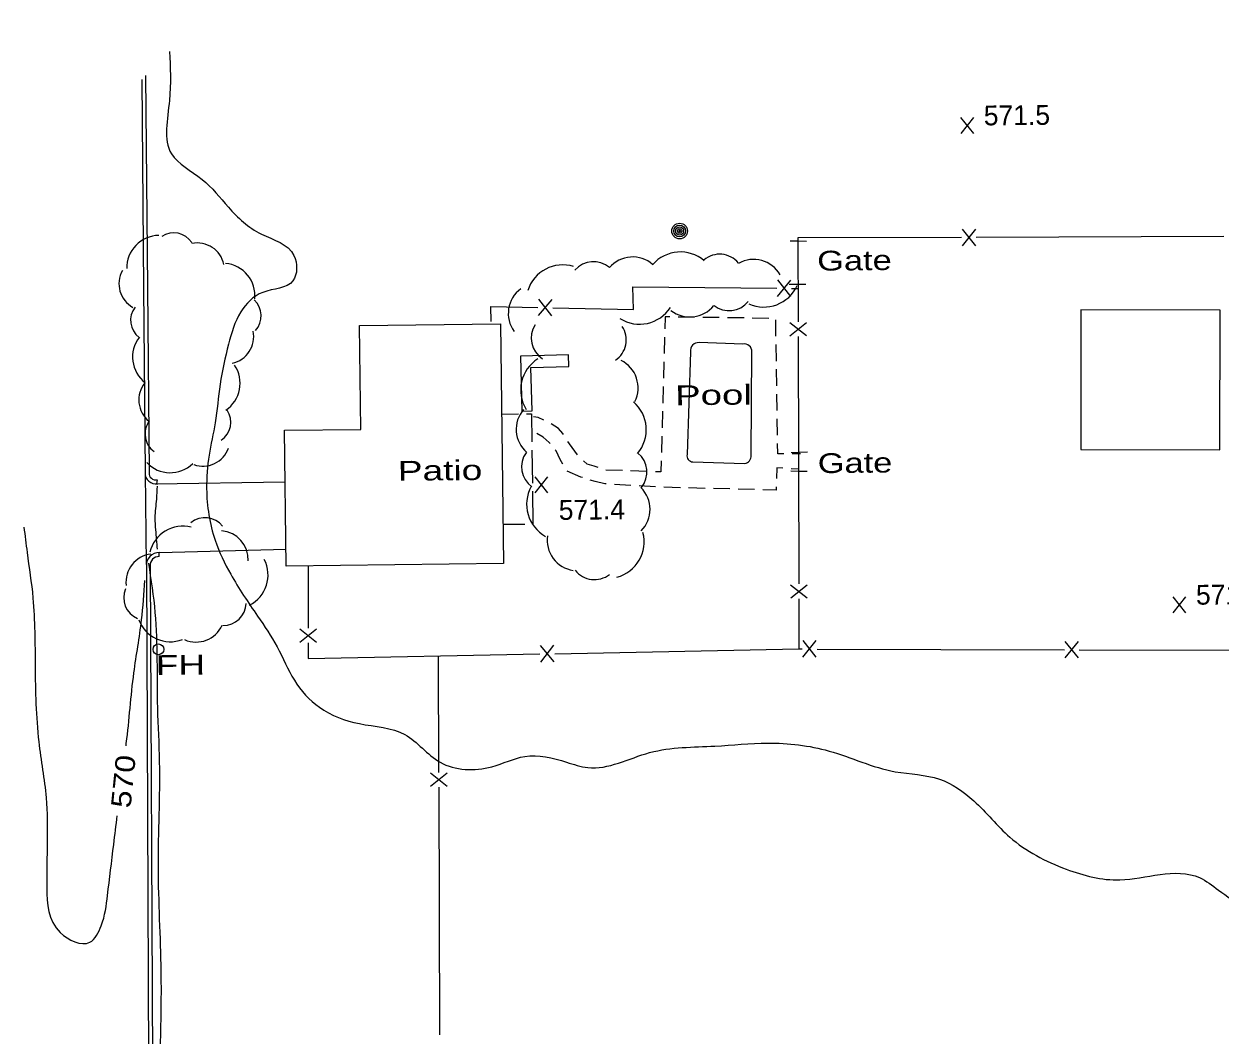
# Model space of a CAD drawing. Extents: x 2361708 to 2370558, y 6977955 to 6991887.
# Drawn here: x 2368271.1 to 2368561.2, y 6990259.1 to 6990504.4 of the extents above; entities that cross this region are included whole.
import ezdxf
from ezdxf.enums import TextEntityAlignment as Align

# ---------------------------------------------------------------- set-up
doc = ezdxf.new("R2010")
doc.units = 0
doc.header["$LTSCALE"] = 1.9
for name, color, linetype, lineweight in [('11', 7, 'Continuous', 25), ('13', 7, 'Continuous', 13), ('14', 7, 'Continuous', 13), ('17', 7, 'Continuous', 25), ('2', 7, 'Continuous', 25), ('20', 7, 'Continuous', 25), ('23', 7, 'Continuous', 25), ('29', 7, 'Continuous', 13), ('31', 7, 'Continuous', 13), ('35', 7, 'Continuous', 13)]:
    doc.layers.add(name, color=color, linetype=linetype, lineweight=lineweight)

msp = doc.modelspace()

# ---------------------------------------------------------------- linework, layer by layer
at = {"layer": '11'}
for points in [[(2368561.178, 6990434.941), (2368527.455, 6990434.98), (2368527.418, 6990401.138), (2368561.14, 6990401.099)], [(2368386.711, 6990431.64), (2368387.434, 6990373.474), (2368334.738, 6990372.822), (2368334.334, 6990405.8), (2368352.773, 6990406.026), (2368352.463, 6990431.224)]]:
    msp.add_lwpolyline(points, close=True, dxfattribs=at)
at = {"layer": '13'}
for p, q in [((2368433.738, 6990433.208), (2368429.737, 6990433.27)), ((2368439.739, 6990433.125), (2368435.738, 6990433.177)), ((2368445.74, 6990433.042), (2368441.739, 6990433.094)), ((2368451.741, 6990432.949), (2368447.74, 6990433.011)), ((2368453.493, 6990428.606), (2368453.425, 6990432.605)), ((2368426.483, 6990428.419), (2368426.371, 6990424.417)), ((2368453.59, 6990422.606), (2368453.522, 6990426.606)), ((2368426.31, 6990422.417), (2368426.198, 6990418.415)), ((2368453.677, 6990416.607), (2368453.619, 6990420.607)), ((2368426.137, 6990416.415), (2368426.026, 6990412.413)), ((2368453.774, 6990410.607), (2368453.706, 6990414.607)), ((2368425.965, 6990410.412), (2368425.853, 6990406.411)), ((2368453.861, 6990404.608), (2368453.803, 6990408.607)), ((2368425.801, 6990404.41), (2368425.69, 6990400.41)), ((2368459.425, 6990400.071), (2368457.424, 6990400.081)), ((2368459.149, 6990396.398), (2368457.149, 6990396.499)), ((2368416.241, 6990396.029), (2368412.239, 6990396.161)), ((2368422.243, 6990395.827), (2368418.242, 6990395.958)), ((2368418.315, 6990392.459), (2368414.323, 6990392.701)), ((2368424.309, 6990392.096), (2368420.316, 6990392.338)), ((2368430.311, 6990391.883), (2368426.31, 6990391.995)), ((2368436.313, 6990391.73), (2368432.312, 6990391.832)), ((2368442.315, 6990391.577), (2368438.314, 6990391.68)), ((2368448.316, 6990391.424), (2368444.315, 6990391.527))]:
    msp.add_line(p, q, dxfattribs=at)
for points in [[(2368427.736, 6990433.301), (2368426.627, 6990433.31), (2368426.544, 6990430.419)], [(2368397.203, 6990408.279), (2368395.838, 6990408.886), (2368394.656, 6990409.045)], [(2368398.697, 6990402.643), (2368398.505, 6990402.881), (2368397.053, 6990404.127), (2368395.534, 6990405.062)], [(2368401.937, 6990404.753), (2368401.765, 6990405.022), (2368400.733, 6990406.232), (2368398.992, 6990407.396)], [(2368405.354, 6990399.826), (2368403.399, 6990402.487), (2368403.023, 6990403.074)], [(2368455.424, 6990400.093), (2368453.934, 6990400.098), (2368453.89, 6990402.608)], [(2368401.796, 6990397.562), (2368401.135, 6990398.706), (2368400.205, 6990400.797), (2368399.962, 6990401.095)], [(2368410.334, 6990396.773), (2368409.39, 6990397.084), (2368407.726, 6990397.558), (2368406.788, 6990398.429)], [(2368425.629, 6990398.409), (2368425.554, 6990395.718), (2368424.244, 6990395.765)], [(2368455.148, 6990396.6), (2368453.717, 6990396.666), (2368453.621, 6990394.105)], [(2368406.537, 6990394.347), (2368406.155, 6990394.473), (2368402.852, 6990395.892)], [(2368412.321, 6990392.822), (2368412.001, 6990392.839), (2368409.666, 6990393.357), (2368408.443, 6990393.745)], [(2368453.54, 6990392.104), (2368453.508, 6990391.293), (2368450.317, 6990391.373)]]:
    msp.add_lwpolyline(points, dxfattribs=at)
at = {"layer": '14'}
for p, q in [((2368387.01, 6990409.722), (2368391.009, 6990409.78)), ((2368394.323, 6990401.011), (2368394.428, 6990393.012)), ((2368394.458, 6990391.012), (2368394.564, 6990383.012)), ((2368392.564, 6990382.983), (2368387.474, 6990382.925))]:
    msp.add_line(p, q, dxfattribs=at)
msp.add_lwpolyline([(2368393.009, 6990409.809), (2368394.199, 6990409.82), (2368394.293, 6990403.011)], dxfattribs=at)
at = {"layer": '17'}
for p, q in [((2368498.668, 6990454.547), (2368501.886, 6990450.557)), ((2368501.868, 6990454.557), (2368498.686, 6990450.547)), ((2368562.078, 6990452.78), (2368502.077, 6990452.589)), ((2368453.871, 6990438.28), (2368457.113, 6990442.251)), ((2368457.071, 6990438.25), (2368453.913, 6990442.28)), ((2368457.293, 6990440.212), (2368458.922, 6990440.197)), ((2368395.922, 6990433.608), (2368399.195, 6990437.549)), ((2368399.123, 6990433.548), (2368395.994, 6990437.609)), ((2368456.861, 6990431.947), (2368460.872, 6990428.756)), ((2368456.871, 6990428.748), (2368460.861, 6990431.956)), ((2368458.854, 6990428.547), (2368459.025, 6990368.545)), ((2368340.008, 6990372.832), (2368340.011, 6990357.832)), ((2368457.046, 6990368.346), (2368461.057, 6990365.155)), ((2368457.057, 6990365.146), (2368461.046, 6990368.354)), ((2368459.029, 6990364.945), (2368459.065, 6990352.775)), ((2368338.043, 6990357.633), (2368342.044, 6990354.431)), ((2368338.043, 6990354.433), (2368342.043, 6990357.631)), ((2368399.702, 6990349.67), (2368396.424, 6990353.608)), ((2368396.502, 6990349.609), (2368399.624, 6990353.669)), ((2368460.044, 6990350.804), (2368463.256, 6990354.795)), ((2368463.244, 6990350.794), (2368460.056, 6990354.804)), ((2368463.455, 6990352.767), (2368523.46, 6990352.598)), ((2368523.639, 6990350.629), (2368526.851, 6990354.62)), ((2368526.839, 6990350.62), (2368523.65, 6990354.629)), ((2368371.756, 6990322.842), (2368371.679, 6990350.853)), ((2368527.06, 6990352.592), (2368582.594, 6990352.44)), ((2368373.738, 6990319.441), (2368369.727, 6990322.633)), ((2368373.727, 6990322.641), (2368369.738, 6990319.433)), ((2368371.931, 6990259.241), (2368371.77, 6990319.242))]:
    msp.add_line(p, q, dxfattribs=at)
for points in [[(2368456.932, 6990451.789), (2368458.933, 6990451.748), (2368460.933, 6990451.707)], [(2368498.477, 6990452.575), (2368458.776, 6990452.447), (2368458.839, 6990432.147)], [(2368399.365, 6990435.511), (2368418.969, 6990435.137), (2368418.767, 6990440.595), (2368453.692, 6990440.248)], [(2368460.714, 6990441.155), (2368458.714, 6990441.155), (2368456.713, 6990441.156)], [(2368384.405, 6990432.188), (2368384.371, 6990435.798), (2368395.764, 6990435.576)], [(2368457.171, 6990400.419), (2368459.17, 6990400.508), (2368461.17, 6990400.597)], [(2368461.085, 6990395.816), (2368459.085, 6990395.837), (2368457.085, 6990395.858)], [(2368340.015, 6990354.232), (2368340.011, 6990350.492), (2368396.263, 6990351.567)], [(2368399.863, 6990351.631), (2368459.065, 6990352.775), (2368459.855, 6990352.772)]]:
    msp.add_lwpolyline(points, dxfattribs=at)
at = {"layer": '2'}
for p, q in [((2368300.48, 6990395.537), (2368300.782, 6990373.299)), ((2368303.387, 6990393.795), (2368303.226, 6990392.844)), ((2368302.976, 6990392.811), (2368334.423, 6990393.31)), ((2368303.924, 6990375.179), (2368303.915, 6990376.139)), ((2368303.985, 6990376.14), (2368334.679, 6990376.972)), ((2368300.797, 6990372.76), (2368301.377, 6990243.559)), ((2368301.757, 6990372.768), (2368302.336, 6990243.568))]:
    msp.add_line(p, q, dxfattribs=at)
for points in [[(2368299.672, 6990490.884), (2368300.144, 6990440.316), (2368300.48, 6990395.537)], [(2368300.623, 6990491.863), (2368301.104, 6990440.325), (2368301.44, 6990395.546)]]:
    msp.add_lwpolyline(points, dxfattribs=at)
msp.add_lwpolyline([(2368394.342, 6990410.522), (2368394.062, 6990421), (2368403.29, 6990421.238), (2368403.213, 6990424.127), (2368391.505, 6990423.805), (2368391.872, 6990410.458)], close=True, dxfattribs=at)
for centre, radius, start, end in [((2368303.094, 6990395.422), 2.616, 177.47443, 280.17534), ((2368303.094, 6990395.422), 1.656, 177.47443, 280.17534), ((2368303.802, 6990373.12), 3.025, 86.54286, 186.84661), ((2368303.802, 6990373.12), 2.065, 86.54286, 186.84661)]:
    msp.add_arc(centre, radius, start, end, dxfattribs=at)
at = {"layer": '20'}
for centre, radius in [((2368430.129, 6990454.134), 1.9), ((2368430.129, 6990454.134), 1.442), ((2368430.129, 6990454.134), 0.973), ((2368430.129, 6990454.134), 0.539), ((2368430.129, 6990454.134), 0.192), ((2368303.718, 6990352.686), 1.3)]:
    msp.add_circle(centre, radius, dxfattribs=at)
at = {"layer": '23'}
for p, q in [((2368445.43, 6990426.729), (2368434.856, 6990427.068)), ((2368432.798, 6990424.838), (2368431.915, 6990399.939)), ((2368447.477, 6990399.747), (2368447.649, 6990424.83)), ((2368433.362, 6990398.142), (2368445.876, 6990397.742))]:
    msp.add_line(p, q, dxfattribs=at)
for centre, radius, start, end in [((2368434.691, 6990425.157), 1.919, 85.05823, 189.54067), ((2368445.789, 6990424.902), 1.861, 357.78805, 101.09945), ((2368433.414, 6990399.669), 1.524, 169.81041, 268.02108), ((2368445.587, 6990399.612), 1.893, 278.78143, 4.0714)]:
    msp.add_arc(centre, radius, start, end, dxfattribs=at)
at = {"layer": '29'}
for centre, radius, start, end in [((2368303.942, 6990445.159), 7.903, 91.06933, 181.06933), ((2368307.392, 6990448.428), 5.265, 33.15376, 123.15376), ((2368313.173, 6990444.638), 6.589, 11.79409, 101.79409), ((2368430.323, 6990440.162), 8.889, 49.37239, 139.37239), ((2368439.821, 6990442.594), 5.922, 39.61492, 129.61492), ((2368319.233, 6990438.419), 7.903, 354.50006, 84.50006), ((2368401.773, 6990437.033), 8.889, 72.64004, 162.64004), ((2368409.225, 6990440.768), 5.922, 49.24255, 139.24255), ((2368418.731, 6990440.423), 7.411, 49.24421, 139.24421), ((2368448.063, 6990439.836), 7.411, 29.65659, 119.65659), ((2368300.731, 6990441.361), 6.589, 150.90885, 240.90885), ((2368395.982, 6990434.109), 7.411, 126.01755, 216.01755), ((2368450.553, 6990444.58), 8.889, 245.62156, 335.62156), ((2368323.389, 6990433.537), 5.265, 317.60113, 47.60113), ((2368442.14, 6990440.738), 5.922, 231.62598, 321.62598), ((2368302.24, 6990432.489), 5.265, 142.33763, 232.33763), ((2368420.429, 6990440.426), 8.889, 237.30302, 327.30302), ((2368432.638, 6990440.694), 7.411, 231.50118, 321.50118), ((2368400.066, 6990428.123), 5.922, 146.89056, 236.89056), ((2368305.352, 6990423.568), 7.903, 142.333, 232.333), ((2368320.236, 6990428.504), 6.589, 282.09717, 12.09717), ((2368411.25, 6990427.71), 5.922, 303.74033, 33.74033), ((2368400.469, 6990415.608), 8.889, 122.07052, 212.07052), ((2368412.643, 6990416.083), 7.411, 333.68994, 63.68994), ((2368315.637, 6990417.223), 7.903, 303.95871, 33.95871), ((2368305.554, 6990413.16), 6.589, 141.21701, 231.21701), ((2368397.904, 6990406.056), 7.411, 139.32923, 229.32923), ((2368413.143, 6990405.963), 8.889, 319.43859, 49.43859), ((2368305.747, 6990404.923), 5.265, 144.16055, 234.16055), ((2368316.015, 6990407.773), 5.265, 303.37291, 33.37291), ((2368314.531, 6990403.702), 6.589, 250.32566, 340.32566), ((2368397.712, 6990396.964), 5.922, 144.75484, 234.75484), ((2368416.263, 6990395.669), 5.922, 320.90958, 50.90958), ((2368306.591, 6990403.43), 7.903, 223.68311, 313.68311), ((2368401.916, 6990387.869), 8.889, 151.05697, 241.05697), ((2368415.537, 6990386.62), 7.411, 315.4291, 45.4291), ((2368309.65, 6990374.298), 8.251, 76.07497, 166.07497), ((2368315.011, 6990379.098), 5.497, 38.74011, 128.74011), ((2368318.599, 6990374.555), 6.879, 356.59397, 86.59397), ((2368405.428, 6990379.147), 7.411, 171.41552, 261.41552), ((2368412.633, 6990378.792), 8.889, 284.72387, 14.72387), ((2368302.718, 6990368.963), 6.879, 96.63949, 186.63949), ((2368322.049, 6990370.765), 8.251, 296.98324, 26.98324), ((2368409.473, 6990375.515), 5.922, 217.98232, 307.98232), ((2368300.801, 6990365.216), 5.497, 156.68792, 246.68792), ((2368319.506, 6990363.994), 5.497, 268.21911, 358.21911), ((2368306.652, 6990362.783), 8.251, 200.75299, 290.75299), ((2368312.859, 6990361.334), 6.879, 246.14099, 336.14099)]:
    msp.add_arc(centre, radius, start, end, dxfattribs=at)
at = {"layer": '31'}
for p, q in [((2368501.477, 6990477.784), (2368498.36, 6990481.635)), ((2368498.397, 6990477.755), (2368501.44, 6990481.665)), ((2368398.201, 6990390.667), (2368395.084, 6990394.518)), ((2368395.121, 6990390.638), (2368398.164, 6990394.547)), ((2368552.926, 6990361.549), (2368549.809, 6990365.399)), ((2368549.846, 6990361.519), (2368552.889, 6990365.429))]:
    msp.add_line(p, q, dxfattribs=at)
at = {"layer": '31', "lineweight": 25}
for points in [[(2368303.467, 6990376.975), (2368303.102, 6990381.652), (2368302.934, 6990384.62), (2368303.321, 6990389.124), (2368303.471, 6990392.256)], [(2368271.104, 6990382.327), (2368271.873, 6990376.194), (2368273.288, 6990365.137), (2368273.825, 6990348.652), (2368274.71, 6990330.269), (2368276.48, 6990316.705), (2368276.647, 6990294.905), (2368279.89, 6990284.026), (2368287.073, 6990281.664), (2368289.856, 6990285.651), (2368291.386, 6990293.006), (2368292.878, 6990305.371), (2368293.752, 6990312.339)], [(2368303.819, 6990241.232), (2368304.159, 6990253.776), (2368304.401, 6990274.559), (2368303.721, 6990299.874), (2368304.018, 6990325.408), (2368303.563, 6990338.504), (2368302.973, 6990361.589), (2368301.369, 6990373.555)], [(2368295.86, 6990329.32), (2368295.935, 6990329.891), (2368297.781, 6990347.02), (2368299.64, 6990359.818), (2368300.409, 6990369.405)]]:
    msp.add_spline(points, degree=3, dxfattribs=at)
at = {"layer": '35'}
for points in [[(2368544.877, 6990563.132), (2368536.747, 6990557.784), (2368526.442, 6990554.096), (2368517.961, 6990553.105), (2368508.153, 6990552.892), (2368494.789, 6990553.254), (2368479.151, 6990554.966), (2368465.744, 6990555.668), (2368454.555, 6990553.351), (2368443.478, 6990546.746), (2368435.844, 6990539.773), (2368438.47, 6990536.978), (2368448.583, 6990534.714), (2368464.262, 6990534.863), (2368481.698, 6990535.369), (2368505.619, 6990536.417), (2368521.205, 6990534.815), (2368537.105, 6990535.986), (2368549.594, 6990538.266), (2368558.375, 6990539.189), (2368564.618, 6990534.678), (2368567.629, 6990524.177), (2368568.907, 6990512.768), (2368571.719, 6990493.614), (2368573.061, 6990472.486), (2368573.839, 6990459.092), (2368574.341, 6990445.127), (2368576.998, 6990431.881), (2368576.21, 6990420.043), (2368576.637, 6990402.516), (2368578.913, 6990390.297), (2368580.542, 6990378.922), (2368580.936, 6990372.226), (2368582.356, 6990369.019), (2368584.836, 6990370.143), (2368584.866, 6990370.123)], [(2368983.929, 6990531.529), (2368979.435, 6990519.356), (2368975.701, 6990506), (2368972.153, 6990495.326), (2368965.023, 6990482.667), (2368952.28, 6990464.985), (2368944.692, 6990449.112), (2368936.279, 6990436.661), (2368930.708, 6990428.388), (2368926.974, 6990420.332), (2368923.178, 6990407.345), (2368925.818, 6990397.9), (2368929.492, 6990388.004), (2368932.253, 6990381.66), (2368935.154, 6990377.288), (2368935.872, 6990367.074), (2368936.658, 6990350.711), (2368934.899, 6990336.894), (2368925.545, 6990315.203), (2368919.061, 6990298.721), (2368917.665, 6990291.017), (2368922.007, 6990291.848), (2368928.932, 6990298.725), (2368940.303, 6990308.073), (2368954.807, 6990321.422), (2368956.934, 6990318.642), (2368952.658, 6990309.771), (2368947.879, 6990300.145), (2368939.818, 6990283.488), (2368927.075, 6990259.465), (2368910.767, 6990240.319), (2368886.835, 6990212.09), (2368866.726, 6990187.627), (2368845.138, 6990163.161), (2368822.496, 6990139.104), (2368799.648, 6990117.845), (2368778.178, 6990104.05), (2368756.592, 6990085.654), (2368734.588, 6990065.974), (2368713.09, 6990048.828), (2368704.692, 6990045.508), (2368705.15, 6990046.662), (2368709.481, 6990052.884), (2368718.059, 6990061.596), (2368727.733, 6990071.708), (2368736.854, 6990082.166), (2368748.659, 6990097.399), (2368759.795, 6990109.476), (2368764.382, 6990117.239), (2368763.943, 6990120.186), (2368757.319, 6990118.552), (2368746.862, 6990109.793), (2368726.432, 6990091.817), (2368699.934, 6990071.484), (2368679.435, 6990058.628), (2368654.88, 6990046.464), (2368626.237, 6990035.071), (2368603.78, 6990024.176), (2368586.487, 6990016.992), (2368573.437, 6990012.767), (2368565.504, 6990008.782), (2368560.239, 6990006.131), (2368556.575, 6990003.426)], [(2368306.448, 6990497.689), (2368306.381, 6990485.798), (2368306.875, 6990472.862), (2368314.304, 6990466.652), (2368320.698, 6990459.913), (2368328.691, 6990453.379), (2368336.59, 6990448.214), (2368336.349, 6990442.051), (2368329.045, 6990439.251), (2368323.69, 6990434.51), (2368320.725, 6990426.672), (2368318.707, 6990416.992), (2368317.476, 6990407.6), (2368316.021, 6990399.796), (2368315.408, 6990391.629), (2368317.477, 6990379.128), (2368321.246, 6990370.894), (2368327.763, 6990360.765), (2368332.504, 6990353.3), (2368336.691, 6990345.189), (2368342.784, 6990338.627), (2368352.452, 6990334.669), (2368363.488, 6990332.014), (2368372.052, 6990325.315), (2368384.563, 6990324.204), (2368392.56, 6990326.71), (2368402.723, 6990325.327), (2368407.846, 6990324.006), (2368422.852, 6990327.639), (2368438.688, 6990329.22), (2368451.482, 6990329.952), (2368466.361, 6990328.033), (2368482.419, 6990323.016), (2368493.157, 6990321.208), (2368501.477, 6990315.947), (2368510.222, 6990307.129), (2368523.896, 6990299.38), (2368536.862, 6990296.773), (2368546.63, 6990298.096), (2368556.237, 6990297.327), (2368560.836, 6990294.291), (2368565.853, 6990289.448), (2368566.111, 6990283.381), (2368566.362, 6990276.913), (2368567.176, 6990266.04), (2368565.907, 6990257.547), (2368568.272, 6990250.659), (2368572.868, 6990246.913), (2368578.046, 6990248.202), (2368585.128, 6990249.11), (2368588.446, 6990258.812), (2368586.77, 6990269.917), (2368591.867, 6990273.325), (2368601.012, 6990272.882), (2368610.964, 6990270.667), (2368622.374, 6990268.575), (2368629.997, 6990270.408), (2368635.673, 6990267.712), (2368641.529, 6990259.787), (2368648.359, 6990254.482), (2368652.762, 6990249.023), (2368658.453, 6990244.678), (2368661.468, 6990246.326), (2368666.518, 6990251.565), (2368673.531, 6990255.492), (2368677.989, 6990258.934), (2368680.855, 6990262.412), (2368681.559, 6990266.208), (2368681.94, 6990269.322), (2368682.334, 6990271.016)], [(2368789.929, 6990320.343), (2368790.53, 6990320.348), (2368797.873, 6990325.298), (2368807.423, 6990333.68), (2368817.733, 6990344.318), (2368829.52, 6990357.271), (2368840.79, 6990369.879), (2368857.89, 6990388.953), (2368868.503, 6990400.184), (2368882.774, 6990414.871), (2368900.904, 6990433.954), (2368914.357, 6990446.283), (2368927.592, 6990458.41), (2368938.738, 6990467.296), (2368945.543, 6990470.961), (2368944.236, 6990466.448), (2368939.885, 6990460.207), (2368933.405, 6990450.725), (2368923.326, 6990435.878), (2368917.886, 6990422.216), (2368911.041, 6990411.13), (2368905.079, 6990401.823), (2368900.974, 6990394.023), (2368900.322, 6990384.766), (2368901.314, 6990374.025), (2368904.437, 6990367.355), (2368904.31, 6990359.763), (2368903.563, 6990354.106), (2368901.129, 6990347.222), (2368896.475, 6990339.217), (2368894.175, 6990318.195), (2368888.579, 6990298.791), (2368874.725, 6990269.767), (2368859.183, 6990244.758), (2368839.662, 6990217.401), (2368811.187, 6990186.269), (2368782.802, 6990157.217), (2368754.567, 6990130.256), (2368727.088, 6990107.924), (2368698.455, 6990089.211), (2368672.208, 6990074.11), (2368648.698, 6990060.265), (2368628.721, 6990050.445), (2368613.068, 6990044.306), (2368603.074, 6990040.52), (2368593.252, 6990034.387), (2368582.867, 6990026.477), (2368572.981, 6990018.563), (2368564.602, 6990014.263), (2368560.596, 6990012.755), (2368556.513, 6990009.896), (2368554.167, 6990007.363), (2368553.067, 6990006.373)], [(2368877.387, 6990324.285), (2368874.297, 6990316.825), (2368865.769, 6990299.724), (2368854.408, 6990277.794), (2368838.655, 6990248.533), (2368821.319, 6990221.817), (2368800.752, 6990198.29), (2368778.177, 6990174.574), (2368756.711, 6990151.938), (2368726.394, 6990125.228), (2368701.09, 6990109.767), (2368674.264, 6990092.341), (2368654.195, 6990079.599), (2368641.287, 6990072.956), (2368627.876, 6990063.548), (2368616.531, 6990055.609), (2368597.914, 6990041.572), (2368580.439, 6990029.435), (2368569.832, 6990023.723), (2368563.015, 6990022.318), (2368556.088, 6990018.872), (2368551.515, 6990012.829), (2368551.072, 6990011.074), (2368549.464, 6990009.759)]]:
    msp.add_spline(points, degree=3, dxfattribs=at)

# ---------------------------------------------------------------- texts
at = {"layer": '14', "width": 1.4}
msp.add_text('Patio', height=4.8, rotation=0.545, dxfattribs=at).set_placement((2368361.802, 6990393.571))
at = {"layer": '17', "width": 1.3}
for p in [(2368463.502, 6990444.512), (2368463.639, 6990395.41)]:
    msp.add_text('Gate', height=4.8, rotation=0.545, dxfattribs=at).set_placement(p)
at = {"layer": '20', "width": 1.4}
msp.add_text('  FH', height=4.8, rotation=0.545, dxfattribs=at).set_placement((2368298.098, 6990346.413))
at = {"layer": '23', "width": 1.45}
msp.add_text('Pool', height=4.8, rotation=0.545, dxfattribs=at).set_placement((2368429.041, 6990411.882))
at = {"layer": '31'}
for s, p in [('571.5', (2368503.918, 6990479.748)), ('571.4', (2368400.834, 6990384.082)), ('571.2', (2368555.367, 6990363.512))]:
    msp.add_text(s, height=4.8, rotation=0.545, dxfattribs=at).set_placement(p)
at = {"layer": '31', "width": 1.2}
msp.add_text(' 570 ', height=4.8, rotation=84.239, dxfattribs=at).set_placement((2368297.599, 6990320.421), align=Align.CENTER)

doc.saveas('drawing.dxf')
